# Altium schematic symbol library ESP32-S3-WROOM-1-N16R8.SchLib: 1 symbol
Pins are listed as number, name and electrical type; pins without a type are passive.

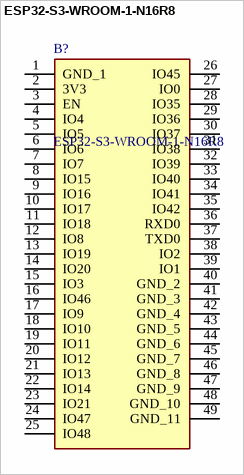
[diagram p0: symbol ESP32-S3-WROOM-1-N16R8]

## ESP32-S3-WROOM-1-N16R8
designator B?
Multiprotocol Modules SMD Module, ESP32-S3R8, 3.3V, 8 MB Octal PSRAM Die, 16 MB Quad SPI Flash, PCB Antenna; Manufacturer_Name: Espressif Systems; Geometry.Height: 3.25mm
footprint ESP32S3WROOM1N16R8
pins: 1 GND_1, 2 3V3, 3 EN, 4 IO4, 5 IO5, 6 IO6, 7 IO7, 8 IO15, 9 IO16, 10 IO17, 11 IO18, 12 IO8, 13 IO19, 14 IO20, 15 IO3, 16 IO46, 17 IO9, 18 IO10, 19 IO11, 20 IO12, 21 IO13, 22 IO14, 23 IO21, 24 IO47, 25 IO48, 26 IO45, 27 IO0, 28 IO35, 29 IO36, 30 IO37, 31 IO38, 32 IO39, 33 IO40, 34 IO41, 35 IO42, 36 RXD0, 37 TXD0, 38 IO2, 39 IO1, 40 GND_2, 41 GND_3, 42 GND_4, 43 GND_5, 44 GND_6, 45 GND_7, 46 GND_8, 47 GND_9, 48 GND_10, 49 GND_11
